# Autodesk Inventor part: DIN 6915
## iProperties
Author: Cor de Vlaming
Shininess: 64.0
Angle Display Precision: 2
Document Length Units: 11269
Document Angle Units: 11283
Document Time Units: 11279
Document Mass Units: 11290
Document Length Units Precision: 3
Document Angle Units Precision: 2
Compacted: True
PropertySet Name: _Private Model Information
Created: 2002-09
Part Number: DIN 6915
Material: Steel, Mild
Description: Moer volgens DIN 934 / ISO 4032
Document SubType Name: Modeling
Designer: Cor de Vlaming
Control State: 0
Master: False
Checked Out: False
PropertySet Name: Design Tracking Control
Density: 0.0
Volumn: 0.0
Area: 0.0
PropertySet Name: Model Information
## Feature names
1. Extrusion1
2. Revolution1
3. Mirror1
4. Chamfer1
5. Extrusion2
